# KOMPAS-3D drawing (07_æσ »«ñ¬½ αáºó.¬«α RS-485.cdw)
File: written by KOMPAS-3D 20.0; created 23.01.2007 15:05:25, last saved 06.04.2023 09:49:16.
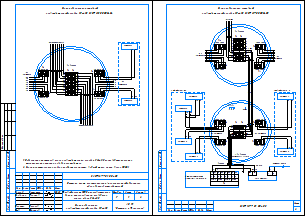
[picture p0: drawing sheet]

Sheets 1-2: A4, portrait

Document properties: Разработал: Антошин; Проверил: Тарасов; Утвердил: Шмончев; Н. контр.: Силаков; Форматы листов документа: 2xA4; Полное имя файла: \\s-tech\depts\Отдел_ПКО\Проекты\Типовые проекты МКД 2023\!Типовой проект\1_Типовой проект МКД_RS-485\07_Сх подкл разв.кор RS-485.cdw

Title block, sheet 1: designation: ВЛСТ 1277. 01. 004 С5; sheet number: 1; Количество листов документа: 2; organisation: АО ГК / "Системы и Технологии"; Форматы листов документа: A3; stored path: C:\Program Files\ASCON\KOMPAS-3D V8 Plus\Templates\Чертеж строительный зданий и сооружений.cdt; cell 302: Система учета электроэнергии (с организацией удаленного / сбора данных) потребителей; cell 303: Типовой проект ИСУЭ многоквартирного / дома с использованием проводного / канала связи RS-485; cell 304: Схема подключения / разветвительной коробки RS-485; cell 320: Р
Title block, sheet 2: sheet number: 2; Форматы листов документа: A4; stored path: H:\Проекты\Владимирские коммунальные системы\Проект\Кольчугинский узел\ПС Кольчугино\С5_002_1_Сх подкл разв.кор RS-485 .cdw; designation, second copy: ВЛСТ 1277. 01. 004 С5-

Referenced files in \\Helios\отдел_пко\Общая папка Компас\_Addons\Signatures\: Signatures.lfr|Тарасов, Signatures.lfr, Signatures.lfr|Силаков, Signatures.lfr|Шмончев
Referenced files in C:\Program Files\ASCON\KOMPAS-3D V13\Libs\_Addons\Signatures\: Signatures.lfr
Referenced files: qlkzkl.frw, eiczbt.frw, hsklda.frw
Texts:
  Тарасов
  Силаков
  Шмончев
  Normal
  Centerline
  Outline
  Схема подключения пассивной
  разветвительной коробки RS-485 ВЛСТ 215.00.000-04
  Схема подключения активной
  разветвительной коробки RS-485 ВЛСТ 217.00.000-05
  1. Подключение счетчиков через разветвительную коробку RS-485 производить согласно
  техническому описанию завода изготовителя.
  2. Экран магистрального кабеля следует заземлить в одной точке линии (возле УСПД).
  Интеллектуальный
  контроллер SM160-02M
  COM1
  COM2
  COM3
  COM4
  Блок питания
  Счетчик 5
  Счетчик 6
  Счетчик 1
  Счетчик 3
  Счетчик 4
  Счетчик 2
  На счетчики
  RS-485
  Ответвления 1-3
  питание ~230В
  Пит.
  Ответвления 4, 5
  АРК RS-485
  ВЛСТ 217.00.000-05
  РК RS-485
  счетчики
  Разраб.
  Н.контр.
  Утв.
  Антошин
  03 Рабочие чертежи основного комплекта. ГОСТ 21.101-97 Ф3
  05 Чертежи строительных изделий. Посл. листы.  ГОСТ 21.101-97 Ф6
Dimensions and other numbers on the sheet: 1; 2; 3; 4; 5; 6; 7; 8; 02.23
